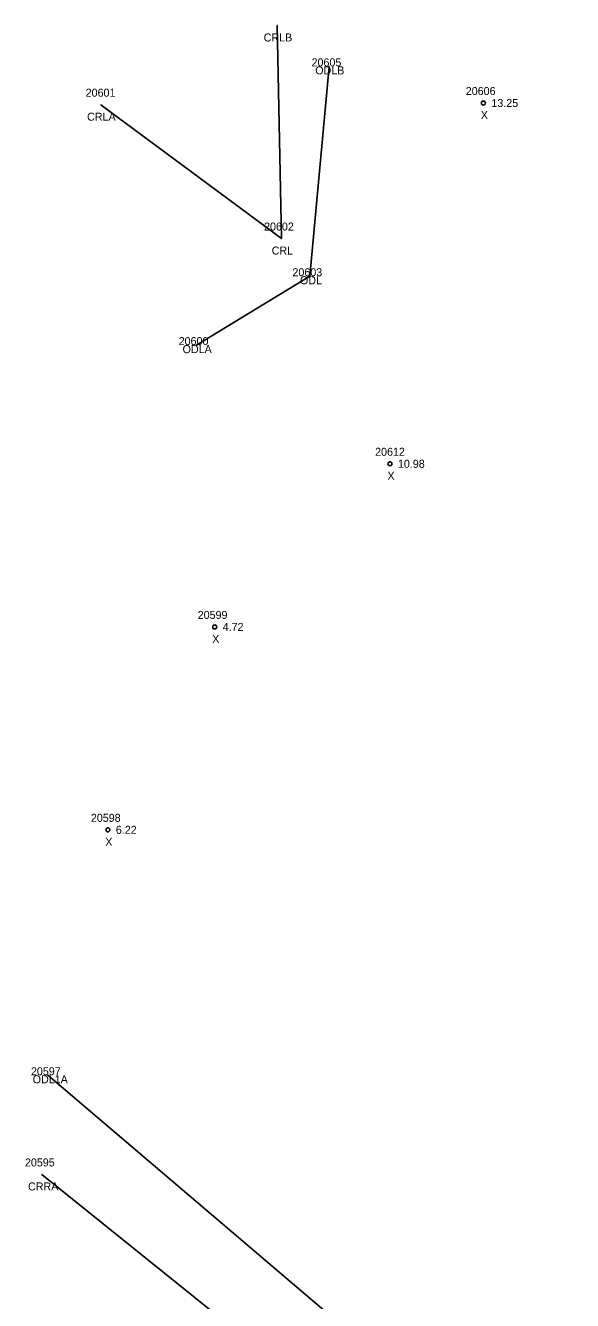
# Model space of a CAD drawing. Extents: x 2432729 to 2433340, y 684958 to 688103.
# Drawn here: x 2432921 to 2432989.3, y 686061.9 to 686221.2 of the extents above; entities that cross this region are included whole.
import ezdxf

# ---------------------------------------------------------------- set-up
doc = ezdxf.new("R2010")
doc.units = 0
for name, color, linetype in [('RD_EX_H2O', 7, 'Continuous'), ('RD_EX_H2O_txCode', 7, 'Continuous'), ('RD_Sketch8', 7, 'Continuous'), ('RD_SMD_Locator', 7, 'Continuous')]:
    doc.layers.add(name, color=color, linetype=linetype)

msp = doc.modelspace()

# ---------------------------------------------------------------- linework, layer by layer
at = {"layer": 'RD_EX_H2O'}
for points in [[(2432930.41, 686211.35), (2432952.98, 686194.62), (2432952.45, 686221.25)], [(2432942.35, 686181.3), (2432956.53, 686189.91), (2432958.92, 686216.14)], [(2432923.79, 686090.04), (2433021.62, 686006.73), (2433104.45, 685963.02), (2433133.66, 685953.1), (2433209.77, 685934.52), (2433322.81, 685903.72)], [(2432923.04, 686077.65), (2433019.93, 685999.69), (2433090.75, 685956.18), (2433102.59, 685949.56), (2433131.31, 685944.06), (2433132.23, 685945.04), (2433164.1, 685935.07), (2433204.66, 685929.9), (2433314.75, 685896.03)]]:
    msp.add_lwpolyline(points, dxfattribs=at)
at = {"layer": 'RD_SMD_Locator'}
for centre, radius in [((2432952.45, 686221.25), 0.001), ((2432958.92, 686216.14), 0.001), ((2432930.41, 686211.35), 0.001), ((2432978.21, 686211.56), 0.25), ((2432952.98, 686194.62), 0.001), ((2432956.53, 686189.91), 0.001), ((2432942.35, 686181.3), 0.001), ((2432966.53, 686166.47), 0.25), ((2432944.63, 686146.08), 0.25), ((2432931.28, 686120.72), 0.25), ((2432923.79, 686090.04), 0.001), ((2432923.04, 686077.65), 0.001)]:
    msp.add_circle(centre, radius, dxfattribs=at)

# ---------------------------------------------------------------- texts
at = {"layer": 'RD_EX_H2O_txCode'}
for s, p in [('CRLB', (2432950.75, 686219.25)), ('20605', (2432956.74, 686216.14)), ('ODLB', (2432957.2, 686215.14)), ('20601', (2432928.51, 686212.35)), ('CRLA', (2432928.69, 686209.35)), ('20602', (2432950.8, 686195.62)), ('CRL', (2432951.75, 686192.62)), ('20603', (2432954.35, 686189.91)), ('ODL', (2432955.29, 686188.91)), ('20600', (2432940.13, 686181.3)), ('ODLA', (2432940.62, 686180.3)), ('20597', (2432921.67, 686090.04)), ('ODL1A', (2432921.89, 686089.04)), ('20595', (2432920.92, 686078.65)), ('CRRA', (2432921.3, 686075.65))]:
    msp.add_text(s, height=1, dxfattribs=at).set_placement(p)
at = {"layer": 'RD_Sketch8'}
for s, p in [('20606', (2432976.01, 686212.56)), ('13.25', (2432979.21, 686211.06)), ('X', (2432977.89, 686209.56)), ('20612', (2432964.68, 686167.47)), ('10.98', (2432967.53, 686165.97)), ('X', (2432966.22, 686164.47)), ('20599', (2432942.51, 686147.08)), ('4.72', (2432945.63, 686145.58)), ('X', (2432944.32, 686144.08)), ('20598', (2432929.16, 686121.72)), ('6.22', (2432932.28, 686120.22)), ('X', (2432930.96, 686118.72))]:
    msp.add_text(s, height=1, dxfattribs=at).set_placement(p)

doc.saveas('drawing.dxf')
